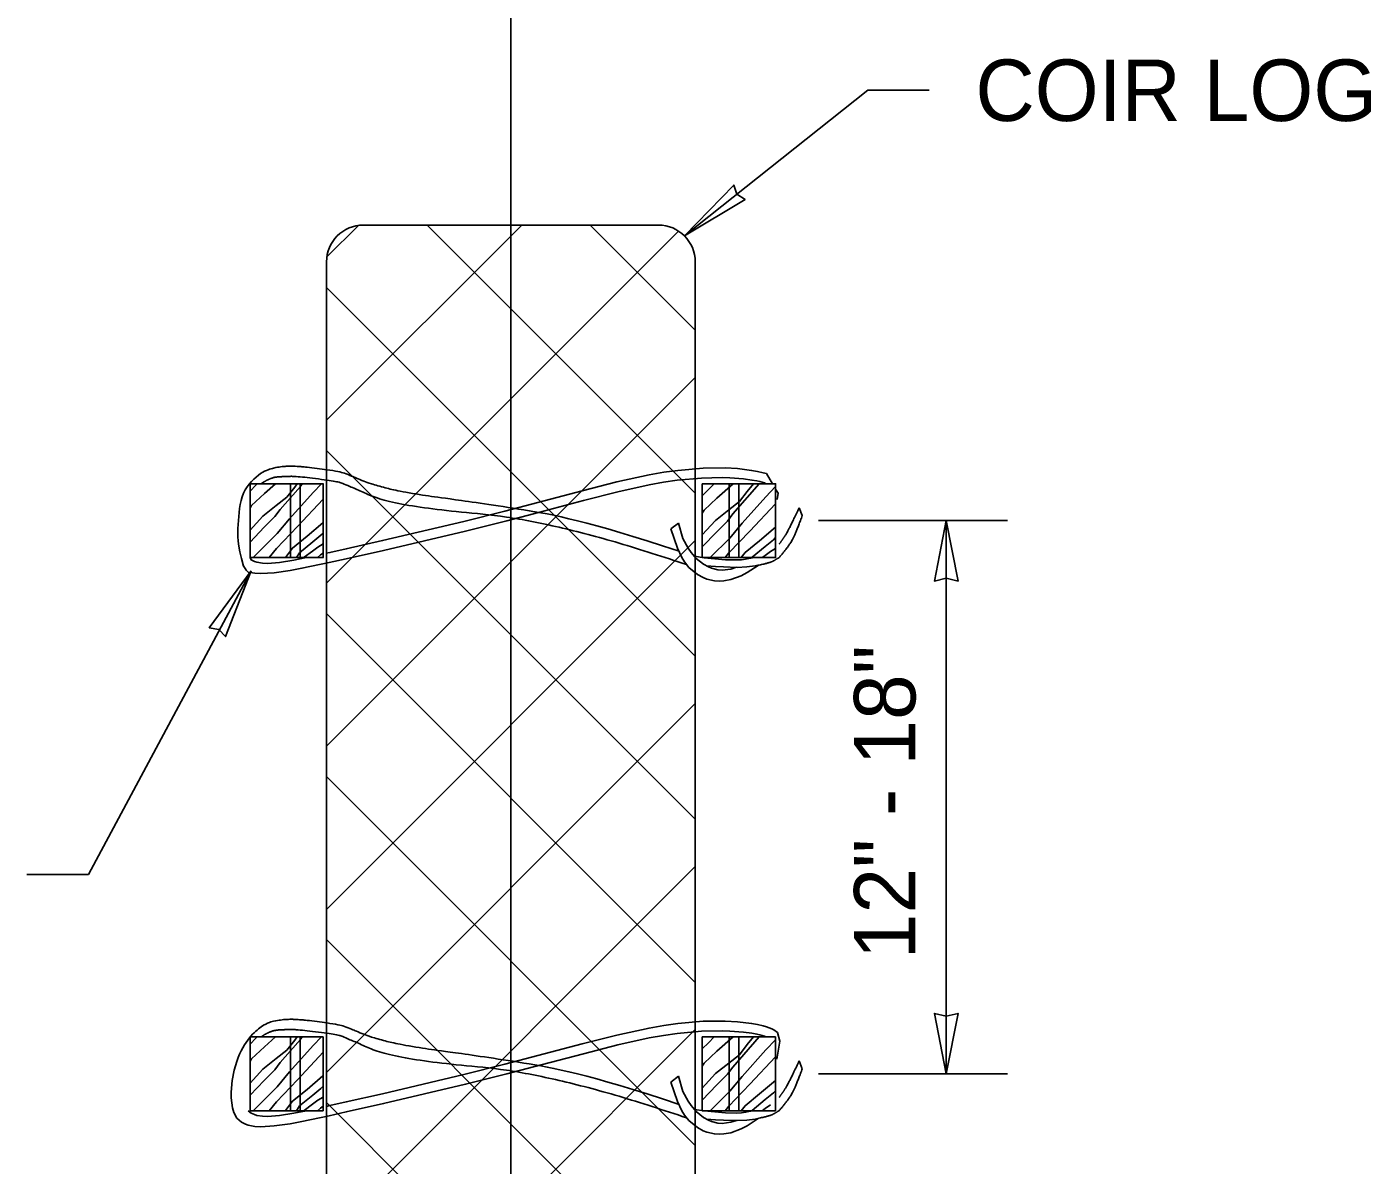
# Model space of a CAD drawing. Extents: x 99862 to 103680, y 99470 to 102076.
# Drawn here: x 101397.2 to 101747.1, y 100962.1 to 101258.4 of the extents above; entities that cross this region are included whole.
import ezdxf

# ---------------------------------------------------------------- set-up
doc = ezdxf.new("R2010")
doc.units = 0
for name, color, linetype in [('Level 10', 7, 'Continuous'), ('Level 15', 7, 'Continuous'), ('Level 20', 7, 'Continuous'), ('Level 3', 7, 'Continuous'), ('Level 4', 7, 'Continuous'), ('Level 6', 7, 'Continuous'), ('Level 8', 7, 'Continuous')]:
    doc.layers.add(name, color=color, linetype=linetype)

msp = doc.modelspace()

# ---------------------------------------------------------------- linework, layer by layer
at = {"layer": 'Level 10'}
msp.add_line((101523.17, 100717.05), (101523.17, 101320.79), dxfattribs=at)
at = {"layer": 'Level 15'}
for p, q in [((101568.36, 101204), (101616.09, 101241.91)), ((101632.09, 101241.91), (101616.09, 101241.91)), ((101652.49, 101129.86), (101603.26, 101129.86)), ((101636.49, 101129.86), (101636.49, 100985.86)), ((101455.55, 101116.82), (101413.18, 101037.72)), ((101397.18, 101037.72), (101413.18, 101037.72)), ((101652.49, 100985.86), (101603.26, 100985.86))]:
    msp.add_line(p, q, dxfattribs=at)
for points in [[(101568.36, 101204), (101584.14, 101213.5), (101581.99, 101214.84), (101581.17, 101217.24)], [(101636.49, 101129.86), (101639.58, 101114.13), (101636.49, 101114.86), (101633.41, 101114.13)], [(101455.55, 101116.82), (101444.67, 101101.96), (101447.17, 101101.55), (101448.86, 101099.66)], [(101636.49, 100985.86), (101639.58, 101001.58), (101636.49, 101000.85), (101633.41, 101001.58)]]:
    msp.add_lwpolyline(points, close=True, dxfattribs=at)
at = {"layer": 'Level 3'}
for p, q in [((101455.27, 101137.58), (101456.8, 101139.11)), ((101455.28, 101139.46), (101455.28, 101120.25)), ((101456.8, 101139.11), (101457.15, 101139.46)), ((101459, 101136.91), (101461.92, 101139.46)), ((101463.14, 101132.76), (101468.98, 101139.46)), ((101465.81, 101120.25), (101465.81, 101139.46)), ((101468.29, 101139.46), (101468.29, 101120.25)), ((101474.35, 101120.25), (101474.35, 101139.46)), ((101474.35, 101139.46), (101474.36, 101139.46)), ((101573, 101139.46), (101573, 101120.25)), ((101573, 101136.33), (101574.62, 101137.95)), ((101574.62, 101137.95), (101576.13, 101139.46)), ((101576.82, 101135.75), (101581.06, 101139.46)), ((101580.02, 101120.25), (101580.02, 101139.46)), ((101580.96, 101131.61), (101587.81, 101139.46)), ((101582.5, 101139.46), (101582.5, 101120.25)), ((101592.08, 101139.46), (101592.08, 101120.25)), ((101592.08, 101139.46), (101592.08, 101120.25)), ((101592.08, 101120.25), (101592.08, 101139.46)), ((101592.08, 101139.46), (101592.08, 101139.46)), ((101585.41, 101127.15), (101592.08, 101134.28)), ((101587.93, 101124.64), (101592.08, 101128.15)), ((101590.74, 101121.82), (101592.08, 101122.64)), ((101455.27, 100995.46), (101455.27, 100976.25)), ((101455.27, 100993.58), (101456.8, 100995.11)), ((101456.8, 100995.11), (101457.15, 100995.46)), ((101459, 100992.91), (101461.92, 100995.46)), ((101463.14, 100988.76), (101468.98, 100995.46)), ((101465.81, 100976.25), (101465.81, 100995.46)), ((101468.29, 100995.46), (101468.29, 100976.25)), ((101474.34, 100976.25), (101474.34, 100995.46)), ((101474.34, 100995.46), (101474.35, 100995.46)), ((101573, 100995.46), (101573, 100976.25)), ((101573, 100992.33), (101574.62, 100993.95)), ((101574.62, 100993.95), (101576.13, 100995.46)), ((101576.82, 100991.75), (101581.06, 100995.46)), ((101580.02, 100976.25), (101580.02, 100995.46)), ((101580.96, 100987.61), (101587.81, 100995.46)), ((101582.5, 100995.46), (101582.5, 100976.25)), ((101592.07, 100976.25), (101592.07, 100995.46)), ((101592.07, 100995.46), (101592.08, 100995.46)), ((101585.41, 100983.15), (101592.08, 100990.28)), ((101587.93, 100980.64), (101592.08, 100984.15))]:
    msp.add_line(p, q, dxfattribs=at)
for points in [[(101455.27, 101133.14), (101455.67, 101133.77), (101459, 101136.91)], [(101474.36, 101139.46), (101474.35, 101139.46), (101455.28, 101139.46)], [(101465.81, 101139.46), (101465.81, 101139.46), (101456.24, 101139.46)], [(101456.24, 101139.46), (101456.24, 101139.46), (101456.24, 101139.46)], [(101462.1, 101133.81), (101464.83, 101135.97), (101466.89, 101138.61), (101467.57, 101139.46)], [(101465.58, 101130.33), (101471.7, 101137.22), (101473.87, 101139.46)], [(101592.08, 101139.46), (101592.08, 101139.46), (101573, 101139.46)], [(101592.08, 101139.46), (101592.08, 101139.46), (101573, 101139.46)], [(101579.92, 101132.65), (101582.65, 101134.81), (101584.71, 101137.45), (101586.3, 101139.46)], [(101582.5, 101139.46), (101582.5, 101139.46), (101592.08, 101139.46)], [(101583.4, 101129.17), (101589.52, 101136.06), (101592.08, 101138.71)], [(101592.08, 101139.46), (101592.08, 101139.46), (101592.08, 101139.46)], [(101455.27, 101127.41), (101458.58, 101131.07), (101462.1, 101133.81)], [(101455.27, 101124.28), (101458.94, 101128.14), (101461.72, 101130.92), (101463.14, 101132.76)], [(101467.6, 101128.31), (101474.28, 101135.46)], [(101573, 101131.85), (101573.49, 101132.61), (101576.82, 101135.75)], [(101573, 101126.15), (101576.4, 101129.91), (101579.92, 101132.65)], [(101456.09, 101120.25), (101462.31, 101126.48), (101465.58, 101130.33)], [(101470.11, 101125.79), (101474.26, 101129.31), (101474.28, 101129.33)], [(101573, 101123.03), (101576.76, 101126.98), (101579.54, 101129.76), (101580.96, 101131.61)], [(101575.06, 101120.25), (101580.13, 101125.32), (101583.4, 101129.17)], [(101460.23, 101120.25), (101462.13, 101122.6), (101467.6, 101128.31)], [(101464.45, 101120.25), (101464.46, 101120.28), (101466.3, 101122.7), (101470.11, 101125.79)], [(101471.59, 101124.31), (101473.7, 101126.04), (101474.28, 101126.64)], [(101578.98, 101120.25), (101579.95, 101121.45), (101585.41, 101127.15)], [(101467.4, 101120.25), (101468.17, 101121.48), (101471.59, 101124.31)], [(101469.29, 101120.25), (101469.33, 101120.32), (101471.54, 101121.95), (101472.93, 101122.98)], [(101472.93, 101122.98), (101474.28, 101123.81)], [(101583.13, 101120.25), (101584.12, 101121.55), (101587.93, 101124.64)], [(101585.95, 101120.25), (101585.99, 101120.32), (101589.41, 101123.16)], [(101589.41, 101123.16), (101591.51, 101124.88), (101592.08, 101125.46)], [(101455.28, 101120.25), (101474.35, 101120.25), (101474.36, 101120.25)], [(101456.24, 101120.25), (101456.24, 101120.25), (101456.24, 101120.25)], [(101472.86, 101120.25), (101473.63, 101120.93), (101474.28, 101121.41)], [(101573, 101120.25), (101592.08, 101120.25), (101592.08, 101120.25)], [(101588.63, 101120.25), (101589.36, 101120.79), (101590.74, 101121.82)], [(101592.08, 101120.25), (101592.08, 101120.25), (101592.08, 101120.25)], [(101474.35, 100995.46), (101474.34, 100995.46), (101455.27, 100995.46)], [(101455.27, 100989.14), (101455.67, 100989.77), (101459, 100992.91)], [(101456.24, 100995.46), (101456.24, 100995.46), (101456.24, 100995.46)], [(101462.1, 100989.81), (101464.83, 100991.97), (101466.89, 100994.61), (101467.57, 100995.46)], [(101465.58, 100986.33), (101471.7, 100993.22), (101473.87, 100995.46)], [(101592.08, 100995.46), (101592.07, 100995.46), (101573, 100995.46)], [(101592.08, 100995.46), (101592.07, 100995.46), (101573, 100995.46)], [(101579.92, 100988.65), (101582.65, 100990.81), (101584.71, 100993.45), (101586.3, 100995.46)], [(101582.5, 100995.46), (101582.5, 100995.46), (101592.07, 100995.46)], [(101583.4, 100985.17), (101589.52, 100992.06), (101592.08, 100994.71)], [(101592.08, 100995.46), (101592.08, 100995.46), (101592.08, 100995.46)], [(101455.27, 100983.41), (101458.58, 100987.07), (101462.1, 100989.81)], [(101467.6, 100984.31), (101474.28, 100991.46)], [(101573, 100987.85), (101573.49, 100988.61), (101576.82, 100991.75)], [(101455.27, 100980.28), (101458.94, 100984.14), (101461.72, 100986.92), (101463.14, 100988.76)], [(101456.09, 100976.25), (101462.31, 100982.48), (101465.58, 100986.33)], [(101573, 100982.15), (101576.4, 100985.91), (101579.92, 100988.65)], [(101573, 100979.03), (101576.76, 100982.98), (101579.54, 100985.76), (101580.96, 100987.61)], [(101460.23, 100976.25), (101462.13, 100978.6), (101467.6, 100984.31)], [(101470.11, 100981.79), (101474.26, 100985.31), (101474.28, 100985.33)], [(101471.59, 100980.31), (101473.7, 100982.04), (101474.28, 100982.64)], [(101575.06, 100976.25), (101580.13, 100981.32), (101583.4, 100985.17)], [(101578.98, 100976.25), (101579.95, 100977.45), (101585.41, 100983.15)], [(101464.45, 100976.25), (101464.46, 100976.28), (101466.3, 100978.7), (101470.11, 100981.79)], [(101467.4, 100976.25), (101468.17, 100977.48), (101471.59, 100980.31)], [(101469.29, 100976.25), (101469.33, 100976.32), (101471.54, 100977.95), (101472.93, 100978.98)], [(101472.93, 100978.98), (101474.28, 100979.81)], [(101583.13, 100976.25), (101584.12, 100977.55), (101587.93, 100980.64)], [(101585.95, 100976.25), (101585.99, 100976.32), (101589.41, 100979.16)], [(101589.41, 100979.16), (101591.51, 100980.88), (101592.08, 100981.46)], [(101455.27, 100976.25), (101474.34, 100976.25), (101474.35, 100976.25)], [(101456.24, 100976.25), (101465.81, 100976.25), (101465.81, 100976.25)], [(101456.24, 100976.25), (101456.24, 100976.25), (101456.24, 100976.25)], [(101472.86, 100976.25), (101473.63, 100976.93), (101474.28, 100977.41)], [(101573, 100976.25), (101580.02, 100976.25), (101580.13, 100976.25), (101592.08, 100976.25)], [(101573, 100976.25), (101592.07, 100976.25), (101592.08, 100976.25)], [(101588.63, 100976.25), (101589.36, 100976.79), (101590.74, 100977.82)], [(101592.08, 100976.25), (101592.08, 100976.25), (101592.08, 100976.25)]]:
    msp.add_lwpolyline(points, dxfattribs=at)
at = {"layer": 'Level 4'}
for p, q in [((101566.81, 101129.22), (101564.85, 101127.72)), ((101566.81, 100985.22), (101564.85, 100983.72))]:
    msp.add_line(p, q, dxfattribs=at)
for points in [[(101475.13, 101121.36), (101476.08, 101121.57), (101480.33, 101122.52), (101489.78, 101124.66), (101510.9, 101129.64), (101521.64, 101132.34), (101528.58, 101134.16), (101541.71, 101137.64), (101550.79, 101139.93), (101559.13, 101141.76), (101562.99, 101142.45), (101566.64, 101142.96), (101573.25, 101143.53), (101578.94, 101143.58), (101582.19, 101143.4), (101585.84, 101142.96), (101587.36, 101142.69), (101588.83, 101142.35), (101589.68, 101142.11), (101591.25, 101139.46)], [(101453.56, 101118.09), (101454.29, 101116.99), (101454.82, 101116.48), (101456.56, 101116.16), (101458.06, 101116.07), (101461.55, 101116.27), (101465.68, 101116.87), (101468.79, 101117.45), (101475.86, 101118.95), (101480.31, 101119.93), (101490.05, 101122.11), (101511.39, 101127.13), (101522.13, 101129.82), (101529.05, 101131.63), (101542.07, 101135.09), (101551.02, 101137.37), (101559.18, 101139.18), (101562.93, 101139.87), (101566.45, 101140.38), (101572.78, 101140.96), (101578.14, 101141.07), (101580.21, 101141), (101583.76, 101140.71), (101585.9, 101140.43), (101587.21, 101140.2), (101587.96, 101140.03), (101589.16, 101139.67), (101589.53, 101139.46)], [(101592.08, 101138.07), (101592.73, 101136.98), (101592.51, 101135.4)], [(101598.2, 101133.2), (101599.02, 101131.17)], [(101581.92, 101117.74), (101580.46, 101117.23), (101578.2, 101116.96), (101577.02, 101117.05), (101575.4, 101117.46), (101574.58, 101117.8), (101573.33, 101118.51), (101571.44, 101120.04), (101570.1, 101121.58), (101569.32, 101122.73), (101567.91, 101125.22), (101566.81, 101129.22)], [(101587.75, 101118.36), (101587.57, 101118.21), (101584.72, 101116.34), (101583.09, 101115.49), (101580.44, 101114.53), (101578.57, 101114.19), (101577.61, 101114.13), (101576.16, 101114.2), (101574.19, 101114.65), (101573.2, 101115.05), (101571.72, 101115.87), (101569.53, 101117.69), (101568.33, 101119.13), (101567.68, 101120.23), (101566.58, 101122.66), (101564.85, 101127.72)], [(101455.28, 101120.25), (101455.54, 101119.63), (101456.39, 101119.23), (101457.04, 101119.03), (101458.55, 101118.79), (101459.85, 101118.75), (101462.93, 101118.98), (101466.64, 101119.57), (101469.96, 101120.25)], [(101586.16, 101120.27), (101586.03, 101120.22), (101584.27, 101119.86), (101583.23, 101119.69), (101582, 101119.63), (101579, 101119.67), (101573.52, 101120.2), (101570.96, 101120.58)], [(101586.77, 101118.09), (101584.57, 101117.8), (101582.12, 101117.67), (101578.53, 101117.8), (101576.43, 101117.91), (101574.08, 101118.07)], [(101451.11, 100986.8), (101450.63, 100984.09), (101450.36, 100981.09), (101450.35, 100979.64), (101450.68, 100976.97), (101451.04, 100975.81), (101451.86, 100974.33), (101453.05, 100973.25), (101454.05, 100972.73), (101454.82, 100972.48), (101456.56, 100972.16), (101458.06, 100972.07), (101461.55, 100972.27), (101465.68, 100972.87), (101468.79, 100973.45), (101475.86, 100974.95), (101480.31, 100975.93), (101490.05, 100978.11), (101511.39, 100983.13), (101522.13, 100985.82), (101529.05, 100987.63), (101542.07, 100991.09), (101551.02, 100993.37), (101559.18, 100995.18), (101562.93, 100995.87), (101566.45, 100996.38), (101572.78, 100996.96), (101578.14, 100997.07), (101580.21, 100997), (101583.76, 100996.71), (101585.9, 100996.43), (101587.21, 100996.2), (101587.96, 100996.03), (101589.16, 100995.67), (101589.53, 100995.46)], [(101475.13, 100977.36), (101476.08, 100977.57), (101480.33, 100978.52), (101489.78, 100980.66), (101510.9, 100985.64), (101521.64, 100988.34), (101528.58, 100990.16), (101541.71, 100993.64), (101550.79, 100995.93), (101559.13, 100997.76), (101562.99, 100998.45), (101566.64, 100998.96), (101573.25, 100999.53), (101578.94, 100999.58), (101582.19, 100999.4), (101585.84, 100998.96), (101587.36, 100998.69), (101588.83, 100998.35), (101589.68, 100998.11), (101591.08, 100997.57), (101591.65, 100997.27), (101592.56, 100996.59), (101593.21, 100994.36), (101592.38, 100989.71)], [(101598.2, 100989.2), (101599.02, 100987.17)], [(101587.75, 100974.36), (101587.57, 100974.21), (101584.72, 100972.34), (101583.09, 100971.49), (101580.44, 100970.53), (101578.57, 100970.19), (101577.61, 100970.13), (101576.16, 100970.2), (101574.19, 100970.65), (101573.2, 100971.05), (101571.72, 100971.87), (101569.53, 100973.69), (101568.33, 100975.13), (101567.68, 100976.23), (101566.58, 100978.66), (101564.85, 100983.72)], [(101581.92, 100973.74), (101580.46, 100973.23), (101578.2, 100972.96), (101577.02, 100973.05), (101575.4, 100973.46), (101574.58, 100973.8), (101573.33, 100974.51), (101571.44, 100976.04), (101570.1, 100977.58), (101569.32, 100978.73), (101567.91, 100981.22), (101566.81, 100985.22)], [(101454.82, 100976.25), (101455.54, 100975.63), (101456.39, 100975.23), (101457.04, 100975.03), (101458.55, 100974.79), (101459.85, 100974.75), (101462.93, 100974.98), (101466.64, 100975.57), (101469.96, 100976.25)], [(101586.16, 100976.27), (101586.03, 100976.22), (101584.27, 100975.86), (101583.23, 100975.69), (101582, 100975.63), (101579, 100975.67), (101573.52, 100976.2), (101570.96, 100976.58)], [(101586.77, 100974.09), (101584.57, 100973.8), (101582.12, 100973.67), (101578.53, 100973.8), (101576.43, 100973.91), (101574.08, 100974.07)]]:
    msp.add_lwpolyline(points, dxfattribs=at)
for points, degree in [([(101453.58, 101118.02), (101451.88, 101123.68), (101452.14, 101128.52), (101452.72, 101137.64), (101458.45, 101142.83), (101461.65, 101143.64), (101463.35, 101143.9), (101463.9, 101143.95), (101464.98, 101144.03), (101465.53, 101144.05), (101466.72, 101144.04), (101467.36, 101144.01), (101468.89, 101143.89), (101469.81, 101143.8), (101472.85, 101143.46), (101475.18, 101143.15), (101478.48, 101142.6), (101479.65, 101142.29), (101481.91, 101141.39), (101482.77, 101141.01), (101484.99, 101140.09), (101486.4, 101139.55), (101490.69, 101138.33), (101493.56, 101137.65), (101501.42, 101136.28), (101506.45, 101135.67), (101525.31, 101132.98), (101542.8, 101129.93), (101566.98, 101121.9)], 3), ([(101458.13, 101139.46), (101460.56, 101141.13), (101464.52, 101141.38), (101467.47, 101141.42), (101477.72, 101140.14), (101479.98, 101139.35), (101493.13, 101133.55), (101534.98, 101129.97), (101568.93, 101118.41)], 2), ([(101593.01, 101123.73), (101594.24, 101125.42), (101595.58, 101127.63), (101598.2, 101133.2)], 2), ([(101592.98, 101120.24), (101594.84, 101122.38), (101597, 101125.61), (101599.02, 101131.17)], 2), ([(101586.77, 101118.09), (101589.9, 101118.74), (101591.51, 101119.31), (101592.98, 101120.24)], 2), ([(101451.11, 100986.8), (101452.84, 100993.28), (101458.33, 100998.8), (101461.65, 100999.64), (101463.35, 100999.9), (101463.9, 100999.95), (101464.98, 101000.03), (101465.53, 101000.05), (101466.72, 101000.04), (101467.36, 101000.01), (101468.89, 100999.89), (101469.81, 100999.8), (101472.85, 100999.46), (101475.18, 100999.15), (101478.48, 100998.6), (101479.65, 100998.29), (101481.91, 100997.39), (101482.77, 100997.01), (101484.99, 100996.09), (101486.4, 100995.55), (101490.69, 100994.33), (101493.56, 100993.65), (101501.42, 100992.28), (101506.45, 100991.67), (101525.31, 100988.98), (101542.8, 100985.93), (101566.98, 100977.9)], 3), ([(101458.13, 100995.46), (101460.56, 100997.13), (101464.52, 100997.38), (101467.47, 100997.42), (101477.72, 100996.14), (101479.98, 100995.35), (101493.13, 100989.55), (101534.98, 100985.97), (101568.93, 100974.41)], 2), ([(101593.01, 100979.73), (101594.24, 100981.42), (101595.58, 100983.63), (101598.2, 100989.2)], 2), ([(101592.98, 100976.24), (101594.84, 100978.38), (101597, 100981.61), (101599.02, 100987.17)], 2), ([(101586.77, 100974.09), (101589.9, 100974.74), (101591.51, 100975.31), (101592.98, 100976.24)], 2)]:
    msp.add_open_spline(points, degree=degree, dxfattribs=at)
at = {"layer": 'Level 6'}
for p, q in [((101475.17, 101155.99), (101526, 101206.81)), ((101475.17, 101198.43), (101483.56, 101206.81)), ((101501.35, 101206.81), (101571.17, 101136.99)), ((101543.79, 101206.81), (101571.17, 101179.43)), ((101475.17, 101113.55), (101566.85, 101205.23)), ((101475.17, 101190.55), (101571.17, 101094.55)), ((101475.17, 101071.11), (101571.17, 101167.11)), ((101475.17, 101148.11), (101571.17, 101052.11)), ((101475.17, 101028.67), (101571.17, 101124.67)), ((101475.17, 101105.67), (101571.17, 101009.67)), ((101475.17, 100986.23), (101571.17, 101082.23)), ((101475.17, 101063.23), (101571.17, 100967.23)), ((101475.17, 100943.79), (101571.17, 101039.79)), ((101475.17, 101020.79), (101571.17, 100924.79)), ((101475.17, 100901.35), (101571.17, 100997.35)), ((101475.17, 100978.35), (101571.17, 100882.35))]:
    msp.add_line(p, q, dxfattribs=at)
at = {"layer": 'Level 8'}
msp.add_line((101475.17, 100755.3), (101475.17, 101197.21), dxfattribs=at)
for points in [[(101561.57, 101206.81), (101554.87, 101206.81), (101550.99, 101206.81), (101546.82, 101206.81), (101542.4, 101206.81), (101537.78, 101206.81), (101532.99, 101206.81), (101528.11, 101206.81), (101523.17, 101206.81), (101518.24, 101206.81), (101513.35, 101206.81), (101508.57, 101206.81), (101503.94, 101206.81), (101499.52, 101206.81), (101495.35, 101206.81), (101484.78, 101206.81)], [(101571.17, 100755.46), (101571.17, 101197.21)]]:
    msp.add_lwpolyline(points, dxfattribs=at)
for centre, start, end in [((101484.78, 101197.21), 90, 180), ((101561.57, 101197.21), 0, 90)]:
    msp.add_arc(centre, 9.6, start, end, dxfattribs=at)

# ---------------------------------------------------------------- texts
at = {"layer": 'Level 20'}
for s, rotation, p in [('COIR LOG', 360, (101644.09, 101233.91)), ('12" - 18"', 90, (101628.49, 101015.66))]:
    msp.add_text(s, height=16, rotation=rotation, dxfattribs=at).set_placement(p)

doc.saveas('drawing.dxf')
